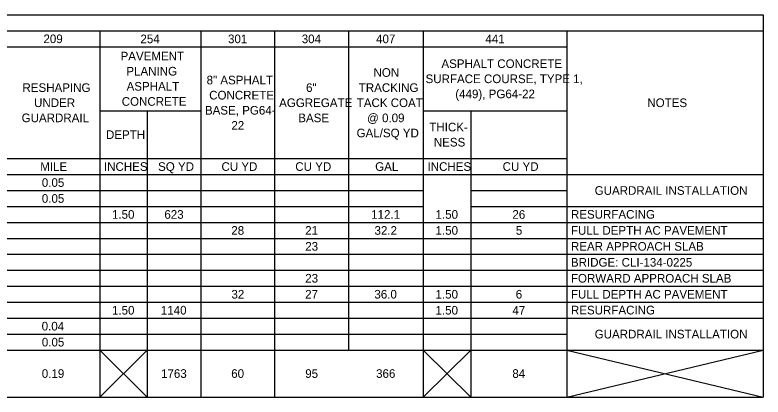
# Model space of a CAD drawing. Extents: x -27.3 to 69.3, y 0 to 30.
# Drawn here: x 57.14 to 69.26, y 15.04 to 21.23 of the extents above; entities that cross this region are included whole.
import ezdxf

# ---------------------------------------------------------------- set-up
doc = ezdxf.new("R2010")
doc.units = 0
doc.layers.add('Default', color=7, linetype='Continuous')

msp = doc.modelspace()

# ---------------------------------------------------------------- linework, layer by layer
at = {"layer": 'Default'}
for p, q in [((42.08, 21.228), (69.257, 21.228)), ((69.257, 21.228), (69.257, 15.036)), ((42.08, 20.969), (69.257, 20.969)), ((58.511, 20.969), (58.511, 15.036)), ((60.149, 20.969), (60.149, 15.036)), ((61.345, 20.969), (61.345, 15.036)), ((62.541, 20.969), (62.541, 15.797)), ((63.753, 20.969), (63.753, 15.036)), ((66.079, 20.969), (66.079, 15.036)), ((49.599, 20.71), (66.079, 20.71)), ((58.511, 19.676), (60.149, 19.676)), ((59.281, 19.676), (59.281, 15.036)), ((63.753, 19.676), (66.079, 19.676)), ((64.523, 19.676), (64.523, 15.036)), ((43.734, 18.9), (66.079, 18.9)), ((42.08, 18.642), (69.257, 18.642)), ((42.08, 18.383), (63.753, 18.383)), ((64.523, 18.383), (66.079, 18.383)), ((42.08, 18.124), (63.753, 18.124)), ((64.523, 18.124), (69.257, 18.124)), ((42.08, 17.866), (69.257, 17.866)), ((42.08, 17.607), (69.257, 17.607)), ((42.08, 17.349), (69.257, 17.349)), ((42.08, 17.09), (69.257, 17.09)), ((42.08, 16.831), (69.257, 16.831)), ((42.08, 16.573), (69.257, 16.573)), ((42.08, 16.314), (66.079, 16.314)), ((66.079, 16.314), (69.257, 16.314)), ((42.08, 16.056), (66.079, 16.056)), ((42.08, 15.797), (66.079, 15.797)), ((58.511, 15.036), (59.281, 15.797)), ((58.511, 15.797), (59.281, 15.036)), ((63.753, 15.036), (64.523, 15.797)), ((63.753, 15.797), (64.523, 15.036)), ((66.079, 15.036), (69.257, 15.797)), ((66.079, 15.797), (69.257, 15.036)), ((66.079, 15.797), (69.257, 15.797)), ((42.08, 15.036), (69.257, 15.036))]:
    msp.add_line(p, q, dxfattribs=at)

# ---------------------------------------------------------------- texts
for s, height, p in [('209', 0.1399, (57.6, 20.771)), ('254', 0.1399, (59.171, 20.77)), ('301', 0.1399, (60.59, 20.77)), ('304', 0.1399, (61.784, 20.77)), ('407', 0.1399, (62.989, 20.77)), ('441', 0.1399, (64.76, 20.77)), ('PAVEMENT ', 0.1399, (58.849, 20.491)), ('ASPHALT CONCRETE ', 0.13995, (64.047, 20.368)), ('PLANING ', 0.1399, (58.943, 20.246)), ('NON ', 0.1399, (62.947, 20.225)), ('8" ASPHALT ', 0.13995, (60.243, 20.103)), ('SURFACE COURSE, TYPE 1, ', 0.13995, (63.79, 20.123)), ('RESHAPING ', 0.1399, (57.26, 19.98)), ('ASPHALT ', 0.1399, (58.947, 20.001)), ('6" ', 0.1399, (61.854, 19.98)), ('TRACKING ', 0.1399, (62.708, 19.98)), ('CONCRETE ', 0.1399, (60.285, 19.858)), ('(449), PG64-22', 0.13995, (64.272, 19.878)), ('UNDER ', 0.1399, (57.448, 19.735)), ('CONCRETE', 0.1399, (58.868, 19.756)), ('AGGREGATE ', 0.1399, (61.418, 19.735)), ('TACK COAT ', 0.1399, (62.675, 19.735)), ('NOTES', 0.1399, (67.383, 19.735)), ('BASE, PG64-', 0.13995, (60.216, 19.613)), ('@ 0.09 ', 0.1399, (62.843, 19.49)), ('GUARDRAIL', 0.1399, (57.247, 19.49)), ('BASE', 0.1399, (61.728, 19.49)), ('22', 0.1399, (60.645, 19.368)), ('GAL/SQ YD', 0.1399, (62.673, 19.245)), ('THICK-', 0.1399, (63.851, 19.341)), ('DEPTH', 0.1399, (58.613, 19.218)), ('NESS', 0.1399, (63.924, 19.096)), ('MILE', 0.1399, (57.548, 18.701)), ('INCHES', 0.1399, (58.58, 18.701)), ('SQ YD', 0.1399, (59.457, 18.701)), ('CU YD', 0.1399, (60.484, 18.701)), ('CU YD', 0.1399, (61.68, 18.701)), ('GAL', 0.1399, (62.974, 18.701)), ('INCHES', 0.1399, (63.822, 18.701)), ('CU YD', 0.1399, (65.039, 18.701)), ('0.05', 0.1399, (57.574, 18.442)), ('GUARDRAIL INSTALLATION', 0.13995, (66.53, 18.313)), ('0.05', 0.1399, (57.574, 18.184)), ('1.50', 0.1399, (58.71, 17.925)), ('623', 0.1399, (59.559, 17.925)), ('112.1', 0.1399, (62.909, 17.925)), ('1.50', 0.1399, (63.952, 17.925)), ('26', 0.1399, (65.197, 17.925)), ('RESURFACING', 0.13995, (66.145, 17.927)), ('28', 0.1399, (60.643, 17.666)), ('21', 0.1399, (61.84, 17.666)), ('32.2', 0.1399, (62.963, 17.666)), ('1.50', 0.1399, (63.952, 17.666)), ('5', 0.14, (65.253, 17.666)), ('FULL DEPTH AC PAVEMENT', 0.13995, (66.145, 17.666)), ('23', 0.1399, (61.841, 17.408)), ('REAR APPROACH SLAB', 0.13995, (66.145, 17.408)), ('BRIDGE: CLI-134-0225', 0.13995, (66.145, 17.149)), ('23', 0.1399, (61.841, 16.891)), ('FORWARD APPROACH SLAB', 0.13995, (66.145, 16.891)), ('32', 0.1399, (60.645, 16.632)), ('27', 0.1399, (61.84, 16.632)), ('36.0', 0.1399, (62.961, 16.632)), ('1.50', 0.1399, (63.952, 16.632)), ('6', 0.14, (65.251, 16.632)), ('FULL DEPTH AC PAVEMENT', 0.13995, (66.145, 16.632)), ('1.50', 0.1399, (58.71, 16.373)), ('1140', 0.1399, (59.502, 16.373)), ('1.50', 0.1399, (63.952, 16.373)), ('47', 0.1399, (65.198, 16.373)), ('RESURFACING', 0.13995, (66.145, 16.375)), ('0.04', 0.1399, (57.571, 16.115)), ('GUARDRAIL INSTALLATION', 0.13995, (66.53, 15.986)), ('0.05', 0.1399, (57.574, 15.856)), ('0.19', 0.1399, (57.573, 15.347)), ('1763', 0.1399, (59.505, 15.347)), ('60', 0.1399, (60.642, 15.347)), ('95', 0.1399, (61.841, 15.347)), ('366', 0.1399, (62.989, 15.347)), ('84', 0.1399, (65.196, 15.347))]:
    msp.add_text(s, height=height, dxfattribs=at).set_placement(p)

doc.saveas('drawing.dxf')
